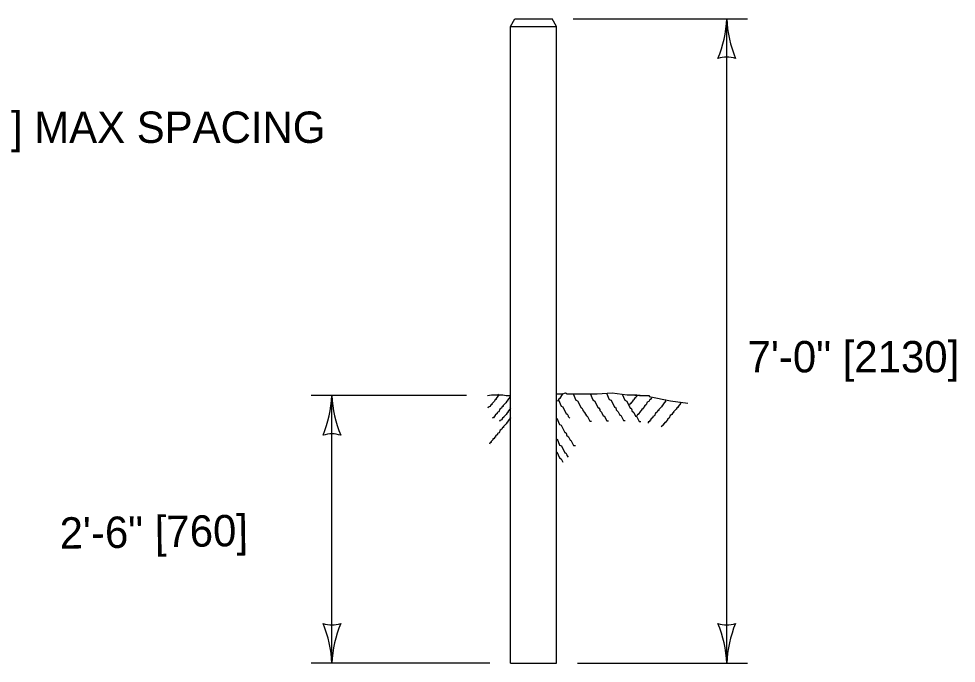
# Model space of a CAD drawing. Extents: x 49991 to 50288, y 49919 to 50011.
# Drawn here: x 50012.585 to 50014.38, y 49988.985 to 49990.218 of the extents above; entities that cross this region are included whole.
import ezdxf

# ---------------------------------------------------------------- set-up
doc = ezdxf.new("R2010")
doc.units = 0
for name, color, linetype in [('Level 2', 7, 'Continuous'), ('Level 3', 7, 'Continuous'), ('Level 5', 7, 'Continuous'), ('Level 7', 7, 'Continuous')]:
    doc.layers.add(name, color=color, linetype=linetype)

msp = doc.modelspace()

# ---------------------------------------------------------------- linework, layer by layer
at = {"layer": 'Level 3'}
for p, q in [((50013.646123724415, 49990.21760892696), (50013.98030388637, 49990.21760893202)), ((50013.94030388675, 49988.984624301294), (50013.94030388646, 49990.21760893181)), ((50013.442368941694, 49989.496841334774), (50013.14440586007, 49989.496841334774)), ((50013.18440585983, 49988.984624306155), (50013.18440585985, 49989.49684132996)), ((50013.48649406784, 49988.98462431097), (50013.14440586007, 49988.98462431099)), ((50013.654564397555, 49988.98462431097), (50013.98030388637, 49988.98462431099))]:
    msp.add_line(p, q, dxfattribs=at)
for centre, radius, start, end in [((50013.71817038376, 49990.226765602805), 0.2223221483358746, 337.45601141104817, 357.6395197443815), ((50014.17301640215, 49990.22910166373), 0.23299613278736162, 182.82731141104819, 202.0771614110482), ((50013.94030388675, 49990.08939438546), 0.05477454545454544, 72.13881974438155, 107.86118085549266), ((50012.95169334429, 49989.508334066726), 0.23299613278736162, 337.92283858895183, 357.1726885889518), ((50013.40653936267, 49989.50599800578), 0.2223221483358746, 182.36048025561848, 202.5439885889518), ((50013.18440585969, 49989.368626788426), 0.05477454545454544, 72.13881914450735, 107.86118025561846), ((50012.96227235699, 49988.97546763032), 0.2223221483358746, 2.3604802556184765, 22.54398858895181), ((50013.184405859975, 49989.11283884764), 0.054774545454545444, 252.13881914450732, 287.8611802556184), ((50013.41711837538, 49988.973131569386), 0.23299613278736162, 157.9228385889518, 177.17268858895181), ((50013.707591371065, 49988.973131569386), 0.23299613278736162, 2.8273114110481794, 22.077161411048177), ((50013.94030388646, 49989.11283884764), 0.054774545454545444, 252.13881974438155, 287.86118085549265), ((50014.16243738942, 49988.97546763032), 0.2223221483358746, 157.4560114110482, 177.63951974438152)]:
    msp.add_arc(centre, radius, start, end, dxfattribs=at)
at = {"layer": 'Level 5'}
msp.add_line((50013.764049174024, 49989.497735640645), (50013.774693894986, 49989.497735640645), dxfattribs=at)
for points in [[(50013.48236894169, 49989.496841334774), (50013.48964421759, 49989.49829041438), (50013.511609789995, 49989.49829041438), (50013.51830174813, 49989.4966087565), (50013.52669707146, 49989.4966087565)], [(50013.50229999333, 49989.49955599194), (50013.50399898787, 49989.497891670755), (50013.498954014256, 49989.491130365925), (50013.498954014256, 49989.4894140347), (50013.49723768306, 49989.4894140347), (50013.495573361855, 49989.48603338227), (50013.4904763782, 49989.480988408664), (50013.4904763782, 49989.47930675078), (50013.488812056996, 49989.47930675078), (50013.48709572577, 49989.47592609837), (50013.48374974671, 49989.47424444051), (50013.483108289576, 49989.47233740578)], [(50013.52419054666, 49989.49616091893), (50013.5258895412, 49989.49447926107), (50013.52080989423, 49989.48771795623), (50013.52080989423, 49989.486036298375), (50013.51912823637, 49989.486036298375), (50013.5174292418, 49989.48265564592), (50013.512366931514, 49989.477628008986), (50013.512366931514, 49989.47589434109), (50013.51066793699, 49989.47589434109), (50013.508986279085, 49989.47254836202), (50013.505640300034, 49989.47084936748), (50013.50390663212, 49989.46578705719), (50013.50054331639, 49989.46408806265), (50013.50054331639, 49989.462371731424), (50013.49716266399, 49989.45899107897), (50013.49716266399, 49989.457344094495), (50013.49549834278, 49989.457344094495), (50013.49378201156, 49989.45396344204), (50013.49211769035, 49989.45396344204), (50013.49211769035, 49989.45356469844)], [(50013.614665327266, 49989.49962368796), (50013.61623664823, 49989.49997207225), (50013.626378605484, 49989.49997207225), (50013.63142357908, 49989.501636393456), (50013.63483890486, 49989.49997207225), (50013.68714366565, 49989.49997207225), (50013.69222331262, 49989.49997207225), (50013.72095018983, 49989.501636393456), (50013.749607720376, 49989.49829041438), (50013.76819264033, 49989.49829041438), (50013.77322027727, 49989.4966087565), (50013.785061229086, 49989.4966087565), (50013.791787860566, 49989.4966087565), (50013.791787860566, 49989.49490976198), (50013.83233835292, 49989.48646679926), (50013.865731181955, 49989.48217375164)], [(50013.62386478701, 49989.500405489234), (50013.62552910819, 49989.49868915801), (50013.62048413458, 49989.49196252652), (50013.62048413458, 49989.49028086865), (50013.61876780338, 49989.49028086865), (50013.61710348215, 49989.48690021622), (50013.61590961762, 49989.4857022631)], [(50013.64622910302, 49989.49997207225), (50013.651274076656, 49989.4881484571), (50013.654654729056, 49989.48646679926), (50013.661398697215, 49989.472944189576), (50013.66313236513, 49989.472944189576), (50013.66477934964, 49989.46956353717), (50013.66477934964, 49989.46789921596), (50013.66816000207, 49989.46451856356), (50013.67154065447, 49989.4577572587), (50013.67323964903, 49989.4577572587), (50013.678301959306, 49989.44763263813), (50013.68168261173, 49989.44763263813)], [(50013.678700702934, 49989.500405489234), (50013.68376301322, 49989.48858187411), (50013.68716100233, 49989.48690021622), (50013.69390497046, 49989.47337760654), (50013.695603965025, 49989.47337760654), (50013.69728562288, 49989.46999695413), (50013.69728562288, 49989.468332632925), (50013.70066627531, 49989.464951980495), (50013.70404692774, 49989.45819067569), (50013.70571124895, 49989.45819067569), (50013.710808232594, 49989.44806605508), (50013.714188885, 49989.44806605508)], [(50013.71037481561, 49989.50120297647), (50013.71541978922, 49989.4894140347), (50013.718800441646, 49989.48771504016), (50013.72556174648, 49989.47424444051), (50013.72724340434, 49989.47424444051), (50013.72892506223, 49989.47086378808), (50013.72892506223, 49989.4691994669), (50013.732323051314, 49989.46578414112), (50013.735686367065, 49989.45902283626), (50013.73742003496, 49989.45902283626), (50013.742447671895, 49989.448915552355), (50013.74582832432, 49989.448915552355)], [(50013.740332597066, 49989.49955599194), (50013.74539490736, 49989.48771504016), (50013.74879289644, 49989.48603338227), (50013.75553686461, 49989.47254544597), (50013.7572011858, 49989.47254544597), (50013.75891751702, 49989.4691994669), (50013.75891751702, 49989.467465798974), (50013.76229816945, 49989.464085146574), (50013.765678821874, 49989.45734117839), (50013.76732580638, 49989.45734117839), (50013.772405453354, 49989.44719922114), (50013.775786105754, 49989.44719922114)], [(50013.76871274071, 49989.49626202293), (50013.765678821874, 49989.49321076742), (50013.765678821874, 49989.49152910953), (50013.76394515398, 49989.49152910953), (50013.76229816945, 49989.48818313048), (50013.76058183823, 49989.48818313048), (50013.76058183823, 49989.48646679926), (50013.7571838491, 49989.483120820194), (50013.7571838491, 49989.48142182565), (50013.75553686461, 49989.48142182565), (50013.75385520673, 49989.47804117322)], [(50013.617970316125, 49989.48854720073), (50013.62301528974, 49989.47675825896), (50013.626378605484, 49989.47505926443), (50013.63313991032, 49989.461571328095), (50013.63483890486, 49989.461571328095), (50013.636520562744, 49989.45819067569), (50013.636520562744, 49989.4565090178), (50013.63964116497, 49989.453388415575)], [(50013.79615670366, 49989.49210121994), (50013.79476976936, 49989.49069694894), (50013.79476976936, 49989.489015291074), (50013.793070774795, 49989.489015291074), (50013.79138911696, 49989.485669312), (50013.78804313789, 49989.48393564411), (50013.786309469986, 49989.478873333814), (50013.78294615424, 49989.47719167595), (50013.78294615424, 49989.47549268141), (50013.77956550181, 49989.47211202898), (50013.77956550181, 49989.4704303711), (50013.77790118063, 49989.4704303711), (50013.77618484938, 49989.467084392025), (50013.7745205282, 49989.467084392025), (50013.7745205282, 49989.46538539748), (50013.771139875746, 49989.46200474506), (50013.771139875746, 49989.460323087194), (50013.76942354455, 49989.460323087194), (50013.767759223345, 49989.456907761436)], [(50013.82219639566, 49989.48858187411), (50013.823895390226, 49989.48690021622), (50013.81881574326, 49989.48013891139), (50013.81881574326, 49989.47847459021), (50013.81713408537, 49989.47847459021), (50013.81543509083, 49989.47505926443), (50013.81040745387, 49989.46999695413), (50013.81040745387, 49989.468332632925), (50013.80867378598, 49989.468332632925), (50013.80702680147, 49989.464951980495), (50013.80364614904, 49989.4632356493), (50013.80192981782, 49989.458208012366), (50013.798549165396, 49989.4565090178), (50013.798549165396, 49989.45482735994), (50013.79516851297, 49989.45144670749), (50013.79516851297, 49989.449782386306), (50013.79350419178, 49989.449782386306), (50013.791787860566, 49989.446401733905), (50013.79014087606, 49989.446401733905), (50013.79014087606, 49989.44468540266), (50013.789603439, 49989.44416530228)], [(50013.850472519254, 49989.48393564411), (50013.852188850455, 49989.482219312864), (50013.8470918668, 49989.47549268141), (50013.8470918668, 49989.47381102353), (50013.845427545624, 49989.47381102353), (50013.8437112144, 49989.4704303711), (50013.83866624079, 49989.46538539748), (50013.83866624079, 49989.46366906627), (50013.8369845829, 49989.46366906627), (50013.835285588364, 49989.460323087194), (50013.831904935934, 49989.45864142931), (50013.83018860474, 49989.453527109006), (50013.82684262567, 49989.45186278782), (50013.82684262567, 49989.450181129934), (50013.8234966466, 49989.44676580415), (50013.8234966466, 49989.44511881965), (50013.821780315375, 49989.44511881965), (50013.82008132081, 49989.44173816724), (50013.81839966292, 49989.44173816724), (50013.81839966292, 49989.440039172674), (50013.815001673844, 49989.43665852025)], [(50013.52476185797, 49989.47407041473), (50013.52646085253, 49989.47240609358), (50013.521415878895, 49989.46564478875), (50013.521415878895, 49989.4639284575), (50013.5196995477, 49989.4639284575), (50013.51803522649, 49989.46054780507), (50013.51293824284, 49989.455502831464), (50013.51293824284, 49989.4538211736), (50013.51127392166, 49989.4538211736), (50013.50955759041, 49989.45044052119), (50013.50621161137, 49989.448758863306), (50013.50557015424, 49989.4468518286)], [(50013.52482129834, 49989.45600315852), (50013.52650295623, 49989.45433883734), (50013.521423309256, 49989.44757753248), (50013.521423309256, 49989.44586120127), (50013.51977632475, 49989.44586120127), (50013.518059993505, 49989.44251522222), (50013.5130150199, 49989.43745291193), (50013.5130150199, 49989.435753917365), (50013.51133336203, 49989.435753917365), (50013.50963436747, 49989.43237326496), (50013.506253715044, 49989.43069160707), (50013.50453738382, 49989.425611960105), (50013.501156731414, 49989.42393030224), (50013.501156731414, 49989.4222313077), (50013.49777607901, 49989.418850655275), (50013.49777607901, 49989.41716899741), (50013.496111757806, 49989.41716899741), (50013.49446477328, 49989.41378834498), (50013.492731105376, 49989.41378834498), (50013.492731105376, 49989.412089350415), (50013.48935045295, 49989.40874337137), (50013.48935045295, 49989.40702704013), (50013.48766879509, 49989.40702704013), (50013.485969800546, 49989.403681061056)], [(50013.615128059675, 49989.453320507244), (50013.62017303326, 49989.441496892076), (50013.62355368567, 49989.43981523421), (50013.63029765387, 49989.42629262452), (50013.632031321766, 49989.42629262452), (50013.63367830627, 49989.4229119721), (50013.63367830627, 49989.42124765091), (50013.6370589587, 49989.417866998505), (50013.640439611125, 49989.41110569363), (50013.64213860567, 49989.41110569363), (50013.64720091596, 49989.40098107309), (50013.650581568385, 49989.40098107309)], [(50013.6153785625, 49989.41381830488), (50013.620423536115, 49989.40202936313), (50013.62378685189, 49989.40033036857), (50013.630548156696, 49989.38684243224), (50013.63224715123, 49989.38684243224), (50013.63392880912, 49989.383461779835), (50013.63392880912, 49989.38178012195), (50013.63704941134, 49989.37865951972)], [(50013.61488828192, 49989.38925093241), (50013.61996792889, 49989.37742731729), (50013.62334858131, 49989.375762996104), (50013.62659054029, 49989.36922706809)]]:
    msp.add_lwpolyline(points, dxfattribs=at)
at = {"layer": 'Level 7'}
for p, q in [((50013.52649406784, 49990.20298925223), (50013.53493474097, 49990.21760892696)), ((50013.53493474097, 49990.21760892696), (50013.606123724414, 49990.21760892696)), ((50013.614564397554, 49990.20298925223), (50013.606123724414, 49990.21760892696)), ((50013.52649406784, 49990.20298925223), (50013.614564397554, 49990.20298925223)), ((50013.52649406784, 49988.98462431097), (50013.52649406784, 49990.20298925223)), ((50013.614564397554, 49989.99743310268), (50013.614564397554, 49990.20298925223)), ((50013.614564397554, 49988.98462431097), (50013.614564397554, 49989.99743310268)), ((50013.52649406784, 49988.98462431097), (50013.614564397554, 49988.98462431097))]:
    msp.add_line(p, q, dxfattribs=at)

# ---------------------------------------------------------------- texts
at = {"layer": 'Level 2'}
for s, p in [('8" [200] MAX SPACING', (50012.31845848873, 49989.98013549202)), ('7\'-0" [2130]', (50013.98030388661, 49989.541116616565))]:
    msp.add_text(s, height=0.05999999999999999, dxfattribs=at).set_placement(p)
msp.add_text('2\'-6" [760]', height=0.059999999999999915, rotation=0.8490366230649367, dxfattribs=at).set_placement((50012.66369744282, 49989.20360563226))

doc.saveas('drawing.dxf')
